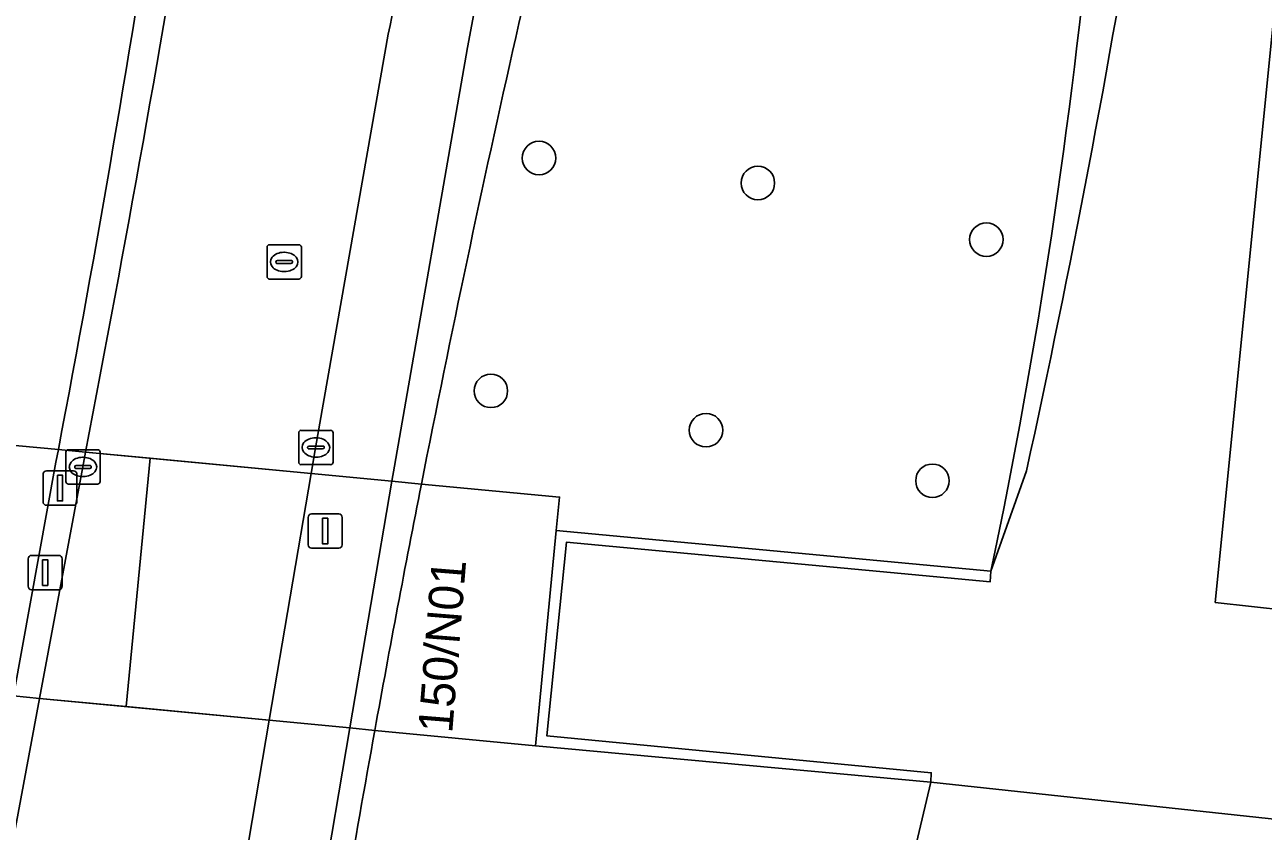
# Model space of a CAD drawing. Extents: x 155018 to 156648, y 383979 to 385733.
# Drawn here: x 156051.04 to 156087.13, y 384751.98 to 384775.48 of the extents above; entities that cross this region are included whole.
import ezdxf

# ---------------------------------------------------------------- set-up
doc = ezdxf.new("R2010")
doc.units = 0
for name, color, linetype in [('IMGEO_Berm_groen', 7, 'Continuous'), ('IMGEO_Boom', 7, 'Continuous'), ('IMGEO_Dek', 7, 'Continuous'), ('IMGEO_Fietspad_gesloten', 7, 'Continuous'), ('IMGEO_Groenvoorziening', 7, 'Continuous'), ('IMGEO_Kolk', 7, 'Continuous'), ('IMGEO_Lichtmast', 7, 'Continuous'), ('IMGEO_Muur', 7, 'Continuous'), ('IMGEO_OVBaan_gesloten', 7, 'Continuous'), ('IMGEO_Pand', 7, 'Continuous'), ('IMGEO_Pand_nummerreeks', 7, 'Continuous'), ('IMGEO_Rioolput', 7, 'Continuous'), ('IMGEO_Verkeersbordpaal', 7, 'Continuous'), ('IMGEO_Verkeerseiland_open', 7, 'Continuous'), ('IMGEO_Voetpad_gesloten', 7, 'Continuous')]:
    doc.layers.add(name, color=color, linetype=linetype)

msp = doc.modelspace()

# ---------------------------------------------------------------- linework, layer by layer
at = {"layer": 'IMGEO_Berm_groen'}
for points in [[(156067.884, 384788.789), (156066.548, 384788.748), (156066.178, 384788.627), (156065.7, 384784.205), (156063.942, 384774.822), (156061.811, 384762.615), (156061.737, 384762.179), (156062.595, 384762.098)], [(156052.017, 384763.102), (156052.807, 384763.027)], [(156062.595, 384762.098), (156061.737, 384762.179), (156060.512, 384754.988), (156061.239, 384754.919)], [(156049.014, 384742.478), (156050.375, 384750), (156051.467, 384755.851), (156050.712, 384755.923), (156049.639, 384750), (156048.252, 384742.596)], [(156061.239, 384754.919), (156060.512, 384754.988), (156059.662, 384750), (156058.567, 384743.52)]]:
    msp.add_lwpolyline(points, dxfattribs=at)
for centre, radius, start, end in [((156534.147, 384669.235), 480.608, 165.6882, 168.85929), ((155377.348, 384893.046), 687.859, 349.104383, 350.635534), ((155599.225, 384849.541), 460.969, 349.19214, 351.42753), ((156522.938, 384671.429), 469.187, 168.85765, 169.74984), ((156558.592, 384665.026), 505.412, 169.75479, 170.32096)]:
    msp.add_arc(centre, radius, start, end, dxfattribs=at)
at = {"layer": 'IMGEO_Boom'}
for centre in [(156066.023, 384771.596), (156072.4, 384770.869), (156079.059, 384769.22), (156064.62, 384764.812), (156070.889, 384763.666), (156077.487, 384762.192)]:
    msp.add_circle(centre, 0.489, dxfattribs=at)
at = {"layer": 'IMGEO_Dek'}
msp.add_lwpolyline([(156066.62, 384761.716), (156062.595, 384762.098), (156061.737, 384762.179), (156059.382, 384762.403), (156052.807, 384763.027), (156052.017, 384763.102), (156050.226, 384763.272), (156050.629, 384767.681), (156049.269, 384767.808), (156048.104, 384767.916), (156043.163, 384768.377), (156042.062, 384756.747), (156046.015, 384756.371), (156047.134, 384756.264), (156050.712, 384755.923), (156051.467, 384755.851), (156058.16, 384755.212), (156060.512, 384754.988), (156061.239, 384754.919), (156065.919, 384754.472), (156066.526, 384760.745)], close=True, dxfattribs=at)
at = {"layer": 'IMGEO_Fietspad_gesloten'}
for points in [[(156049.269, 384767.808), (156050.629, 384767.681), (156050.226, 384763.272), (156052.017, 384763.102)], [(156051.946, 384762.733), (156051.981, 384762.918), (156052.017, 384763.102), (156050.226, 384763.272), (156050.629, 384767.681), (156049.269, 384767.808)], [(156048.455, 384763.527), (156047.134, 384756.264), (156050.712, 384755.923), (156051.946, 384762.733)]]:
    msp.add_lwpolyline(points, dxfattribs=at)
msp.add_arc((155599.225, 384849.541), 460.969, 349.19214, 351.42753, dxfattribs=at)
at = {"layer": 'IMGEO_Groenvoorziening'}
for points in [[(156080.227, 384762.483), (156079.189, 384759.554), (156079.168, 384759.247), (156066.821, 384760.402), (156066.246, 384754.764), (156077.454, 384753.683), (156077.442, 384753.408), (156090.429, 384752.008), (156091.02, 384758.062), (156085.725, 384758.647), (156087.406, 384775.429)], [(156087.406, 384775.429), (156085.725, 384758.647), (156091.02, 384758.062), (156090.429, 384752.008), (156077.442, 384753.408), (156076.635, 384750), (156071.116, 384726.893)], [(156079.189, 384759.554), (156080.227, 384762.483)], [(156061.239, 384754.919), (156065.919, 384754.472), (156066.526, 384760.745), (156066.62, 384761.716), (156062.595, 384762.098)], [(156062.595, 384762.098), (156066.62, 384761.716), (156066.526, 384760.745), (156079.189, 384759.554)], [(156076.635, 384750), (156077.442, 384753.408), (156065.919, 384754.472), (156061.239, 384754.919)]]:
    msp.add_lwpolyline(points, dxfattribs=at)
for centre, radius, start, end in [((155764.34, 384831.717), 323.385, 347.63777, 354.02619), ((155764.34, 384831.717), 323.385, 347.63777, 354.02619), ((156534.147, 384669.235), 480.608, 165.6882, 168.85929), ((155908.116, 384795.42), 174.793, 348.15941, 354.67205), ((155908.116, 384795.42), 174.793, 348.15941, 354.67205), ((156522.938, 384671.429), 469.187, 168.85765, 169.74984), ((156558.592, 384665.026), 505.412, 169.75479, 170.32096)]:
    msp.add_arc(centre, radius, start, end, dxfattribs=at)
at = {"layer": 'IMGEO_Kolk'}
for p, q in [((156059.021, 384762.736), (156059.021, 384763.588)), ((156059.096, 384763.662), (156059.948, 384763.662)), ((156059.509, 384763.442), (156059.534, 384763.442)), ((156060.022, 384763.588), (156060.022, 384762.736)), ((156052.234, 384762.17), (156052.234, 384763.022)), ((156052.309, 384763.096), (156053.161, 384763.096)), ((156053.235, 384763.022), (156053.235, 384762.17)), ((156059.28, 384763.156), (156059.28, 384763.168)), ((156059.718, 384763.119), (156059.32, 384763.119)), ((156059.323, 384763.205), (156059.721, 384763.205)), ((156059.764, 384763.168), (156059.764, 384763.156)), ((156052.493, 384762.59), (156052.493, 384762.602)), ((156052.536, 384762.639), (156052.934, 384762.639)), ((156052.722, 384762.876), (156052.747, 384762.876)), ((156052.977, 384762.602), (156052.977, 384762.59)), ((156059.948, 384762.662), (156059.096, 384762.662)), ((156059.532, 384762.882), (156059.507, 384762.882)), ((156052.931, 384762.553), (156052.533, 384762.553)), ((156052.745, 384762.316), (156052.72, 384762.316)), ((156053.161, 384762.096), (156052.309, 384762.096))]:
    msp.add_line(p, q, dxfattribs=at)
for points in [[(156059.021, 384762.736), (156059.021, 384763.588)], [(156059.096, 384763.662), (156059.948, 384763.662)], [(156060.022, 384763.588), (156060.022, 384762.736)], [(156052.234, 384762.17), (156052.234, 384763.022)], [(156052.309, 384763.096), (156053.161, 384763.096)], [(156053.235, 384763.022), (156053.235, 384762.17)], [(156059.948, 384762.662), (156059.096, 384762.662)], [(156053.161, 384762.096), (156052.309, 384762.096)]]:
    msp.add_lwpolyline(points, dxfattribs=at)
for centre, radius, start, end in [((156059.098, 384763.586), 0.0765, 91.552, 178.448), ((156059.098, 384763.586), 0.0765, 91.552, 178.448), ((156059.946, 384763.586), 0.0765, 1.552, 88.448), ((156059.946, 384763.586), 0.0765, 1.552, 88.448), ((156052.311, 384763.02), 0.0765, 91.552, 178.448), ((156052.311, 384763.02), 0.0765, 91.552, 178.448), ((156053.159, 384763.02), 0.0765, 1.552, 88.448), ((156053.159, 384763.02), 0.0765, 1.552, 88.448), ((156059.32, 384763.165), 0.0403, 85.8775, 175.7526), ((156059.317, 384763.155), 0.0366, 178.938, 274.7102), ((156059.721, 384763.162), 0.043, 264.8664, 352.4533), ((156059.725, 384763.167), 0.0386, 1.7309, 96.639), ((156052.533, 384762.599), 0.0403, 85.8775, 175.7526), ((156052.938, 384762.601), 0.0386, 1.7309, 96.639), ((156059.098, 384762.738), 0.0765, 181.552, 268.448), ((156059.098, 384762.738), 0.0765, 181.552, 268.448), ((156059.946, 384762.738), 0.0765, 271.552, 358.448), ((156059.946, 384762.738), 0.0765, 271.552, 358.448), ((156052.53, 384762.589), 0.0366, 178.938, 274.7102), ((156052.934, 384762.596), 0.043, 264.8664, 352.4533), ((156052.311, 384762.172), 0.0765, 181.552, 268.448), ((156052.311, 384762.172), 0.0765, 181.552, 268.448), ((156053.159, 384762.172), 0.0765, 271.552, 358.448), ((156053.159, 384762.172), 0.0765, 271.552, 358.448)]:
    msp.add_arc(centre, radius, start, end, dxfattribs=at)
for centre, major_axis, ratio, start_param, end_param in [((156059.508, 384763.162), (-0.387, 0.002), 0.722429, 4.712389, 7.853982), ((156059.533, 384763.162), (-0.39, 0.002), 0.717154, 1.570796, 4.712389), ((156052.721, 384762.596), (-0.387, 0.002), 0.722429, 4.712389, 7.853982), ((156052.746, 384762.596), (-0.39, 0.002), 0.717154, 1.570796, 4.712389)]:
    msp.add_ellipse(centre, major_axis=major_axis, ratio=ratio, start_param=start_param, end_param=end_param, dxfattribs=at)
at = {"layer": 'IMGEO_Lichtmast'}
for p, q in [((156051.57, 384761.578), (156051.57, 384762.378)), ((156051.57, 384762.378), (156051.57, 384761.578)), ((156051.67, 384762.478), (156052.46, 384762.478)), ((156052.46, 384762.478), (156051.67, 384762.478)), ((156052.56, 384762.378), (156052.56, 384761.578)), ((156052.56, 384761.578), (156052.56, 384762.378)), ((156052.46, 384761.478), (156051.67, 384761.478)), ((156051.67, 384761.478), (156052.46, 384761.478)), ((156059.396, 384761.226), (156060.186, 384761.226)), ((156060.186, 384761.226), (156059.396, 384761.226)), ((156059.296, 384760.326), (156059.296, 384761.126)), ((156059.296, 384761.126), (156059.296, 384760.326)), ((156060.286, 384761.126), (156060.286, 384760.326)), ((156060.286, 384760.326), (156060.286, 384761.126)), ((156060.186, 384760.226), (156059.396, 384760.226)), ((156059.396, 384760.226), (156060.186, 384760.226))]:
    msp.add_line(p, q, dxfattribs=at)
for points in [[(156051.99, 384762.353), (156052.14, 384762.353), (156052.14, 384761.603), (156051.99, 384761.603), (156051.99, 384762.353)], [(156059.716, 384761.101), (156059.866, 384761.101), (156059.866, 384760.351), (156059.716, 384760.351), (156059.716, 384761.101)]]:
    msp.add_lwpolyline(points, dxfattribs=at)
for centre, start, end in [((156051.67, 384762.378), 90, 180), ((156051.67, 384762.378), 90, 180), ((156052.46, 384762.378), 0, 90), ((156052.46, 384762.378), 360, 90), ((156051.67, 384761.578), 180, 270), ((156051.67, 384761.578), 180, 270), ((156052.46, 384761.578), 270, 0), ((156052.46, 384761.578), 270, 0), ((156059.396, 384761.126), 90, 180), ((156059.396, 384761.126), 90, 180), ((156060.186, 384761.126), 0, 90), ((156060.186, 384761.126), 360, 90), ((156059.396, 384760.326), 180, 270), ((156059.396, 384760.326), 180, 270), ((156060.186, 384760.326), 270, 0), ((156060.186, 384760.326), 270, 0)]:
    msp.add_arc(centre, 0.1, start, end, dxfattribs=at)
at = {"layer": 'IMGEO_Muur'}
msp.add_lwpolyline([(156065.919, 384754.472), (156077.442, 384753.408), (156077.454, 384753.683), (156066.246, 384754.764), (156066.821, 384760.402), (156079.168, 384759.247), (156079.189, 384759.554), (156066.526, 384760.745)], close=True, dxfattribs=at)
at = {"layer": 'IMGEO_OVBaan_gesloten'}
for points in [[(156052.807, 384763.027), (156054.691, 384762.848), (156059.382, 384762.403), (156059.51, 384763.157), (156061.627, 384775.21)], [(156056.254, 384743.988), (156057.275, 384750), (156058.16, 384755.212), (156053.991, 384755.61), (156051.467, 384755.851), (156050.375, 384750), (156049.014, 384742.478)]]:
    msp.add_lwpolyline(points, dxfattribs=at)
msp.add_lwpolyline([(156059.382, 384762.403), (156052.807, 384763.027), (156052.767, 384762.812), (156052.727, 384762.597), (156051.467, 384755.851), (156058.16, 384755.212)], close=True, dxfattribs=at)
for centre, radius, start, end in [((155981.057, 384792.663), 82.438, 347.77742, 353.5016), ((155377.348, 384893.046), 687.859, 349.104383, 350.635534)]:
    msp.add_arc(centre, radius, start, end, dxfattribs=at)
at = {"layer": 'IMGEO_Pand'}
for points in [[(156054.691, 384762.848), (156052.807, 384763.027), (156052.017, 384763.102), (156050.226, 384763.272), (156050.629, 384767.681), (156049.269, 384767.808), (156048.104, 384767.916), (156043.163, 384768.377), (156042.062, 384756.747), (156046.015, 384756.371), (156047.134, 384756.264), (156050.712, 384755.923), (156051.467, 384755.851), (156053.991, 384755.61)], [(156066.526, 384760.745), (156066.62, 384761.716), (156062.595, 384762.098), (156061.737, 384762.179), (156059.382, 384762.403), (156054.691, 384762.848), (156053.991, 384755.61), (156058.16, 384755.212), (156060.512, 384754.988), (156061.239, 384754.919), (156065.919, 384754.472)]]:
    msp.add_lwpolyline(points, close=True, dxfattribs=at)
at = {"layer": 'IMGEO_Rioolput'}
for p, q in [((156058.097, 384768.144), (156058.097, 384768.996)), ((156058.172, 384769.07), (156059.024, 384769.07)), ((156058.585, 384768.85), (156058.61, 384768.85)), ((156059.098, 384768.996), (156059.098, 384768.144)), ((156058.356, 384768.564), (156058.356, 384768.576)), ((156058.794, 384768.527), (156058.396, 384768.527)), ((156058.399, 384768.613), (156058.797, 384768.613)), ((156058.84, 384768.576), (156058.84, 384768.564)), ((156059.024, 384768.07), (156058.172, 384768.07)), ((156058.608, 384768.29), (156058.583, 384768.29))]:
    msp.add_line(p, q, dxfattribs=at)
for points in [[(156058.097, 384768.144), (156058.097, 384768.996)], [(156058.172, 384769.07), (156059.024, 384769.07)], [(156059.098, 384768.996), (156059.098, 384768.144)], [(156059.024, 384768.07), (156058.172, 384768.07)]]:
    msp.add_lwpolyline(points, dxfattribs=at)
for centre, radius, start, end in [((156058.174, 384768.994), 0.0765, 91.552, 178.448), ((156058.174, 384768.994), 0.0765, 91.552, 178.448), ((156059.022, 384768.994), 0.0765, 1.552, 88.448), ((156059.022, 384768.994), 0.0765, 1.552, 88.448), ((156058.396, 384768.573), 0.0403, 85.8775, 175.7526), ((156058.393, 384768.563), 0.0366, 178.938, 274.7102), ((156058.797, 384768.57), 0.043, 264.8664, 352.4533), ((156058.801, 384768.575), 0.0386, 1.7309, 96.639), ((156058.174, 384768.146), 0.0765, 181.552, 268.448), ((156058.174, 384768.146), 0.0765, 181.552, 268.448), ((156059.022, 384768.146), 0.0765, 271.552, 358.448), ((156059.022, 384768.146), 0.0765, 271.552, 358.448)]:
    msp.add_arc(centre, radius, start, end, dxfattribs=at)
for centre, major_axis, ratio, start_param, end_param in [((156058.584, 384768.57), (-0.387, 0.002), 0.722429, 4.712389, 7.853982), ((156058.609, 384768.57), (-0.39, 0.002), 0.717154, 1.570796, 4.712389)]:
    msp.add_ellipse(centre, major_axis=major_axis, ratio=ratio, start_param=start_param, end_param=end_param, dxfattribs=at)
at = {"layer": 'IMGEO_Verkeersbordpaal'}
for p, q in [((156051.139, 384759.118), (156051.139, 384759.918)), ((156051.139, 384759.918), (156051.139, 384759.118)), ((156051.239, 384760.018), (156052.029, 384760.018)), ((156052.029, 384760.018), (156051.239, 384760.018)), ((156052.129, 384759.918), (156052.129, 384759.118)), ((156052.129, 384759.118), (156052.129, 384759.918)), ((156052.029, 384759.018), (156051.239, 384759.018)), ((156051.239, 384759.018), (156052.029, 384759.018))]:
    msp.add_line(p, q, dxfattribs=at)
msp.add_lwpolyline([(156051.559, 384759.893), (156051.709, 384759.893), (156051.709, 384759.143), (156051.559, 384759.143), (156051.559, 384759.893)], dxfattribs=at)
for centre, start, end in [((156051.239, 384759.918), 90, 180), ((156051.239, 384759.918), 90, 180), ((156052.029, 384759.918), 0, 90), ((156052.029, 384759.918), 360, 90), ((156051.239, 384759.118), 180, 270), ((156051.239, 384759.118), 180, 270), ((156052.029, 384759.118), 270, 0), ((156052.029, 384759.118), 270, 0)]:
    msp.add_arc(centre, 0.1, start, end, dxfattribs=at)
at = {"layer": 'IMGEO_Verkeerseiland_open'}
msp.add_lwpolyline([(156052.727, 384762.597), (156052.767, 384762.812), (156052.807, 384763.027), (156052.017, 384763.102), (156051.981, 384762.918), (156051.946, 384762.733), (156050.712, 384755.923), (156051.467, 384755.851)], close=True, dxfattribs=at)
at = {"layer": 'IMGEO_Voetpad_gesloten'}
for points in [[(156063.942, 384774.822), (156065.7, 384784.205), (156066.178, 384788.627), (156063.458, 384787.739), (156062.966, 384783.333)], [(156061.627, 384775.21), (156059.51, 384763.157), (156059.382, 384762.403), (156061.737, 384762.179), (156061.811, 384762.615), (156063.942, 384774.822)], [(156058.567, 384743.52), (156059.662, 384750), (156060.512, 384754.988), (156058.16, 384755.212), (156057.275, 384750), (156056.254, 384743.988)]]:
    msp.add_lwpolyline(points, dxfattribs=at)
msp.add_lwpolyline([(156061.737, 384762.179), (156059.382, 384762.403), (156058.16, 384755.212), (156060.512, 384754.988)], close=True, dxfattribs=at)
msp.add_arc((155981.057, 384792.663), 82.438, 347.77742, 353.5016, dxfattribs=at)

# ---------------------------------------------------------------- texts
at = {"layer": 'IMGEO_Pand_nummerreeks'}
msp.add_text('150/N01', height=1, rotation=85.365, dxfattribs=at).set_placement((156063.492, 384754.819))

doc.saveas('drawing.dxf')
